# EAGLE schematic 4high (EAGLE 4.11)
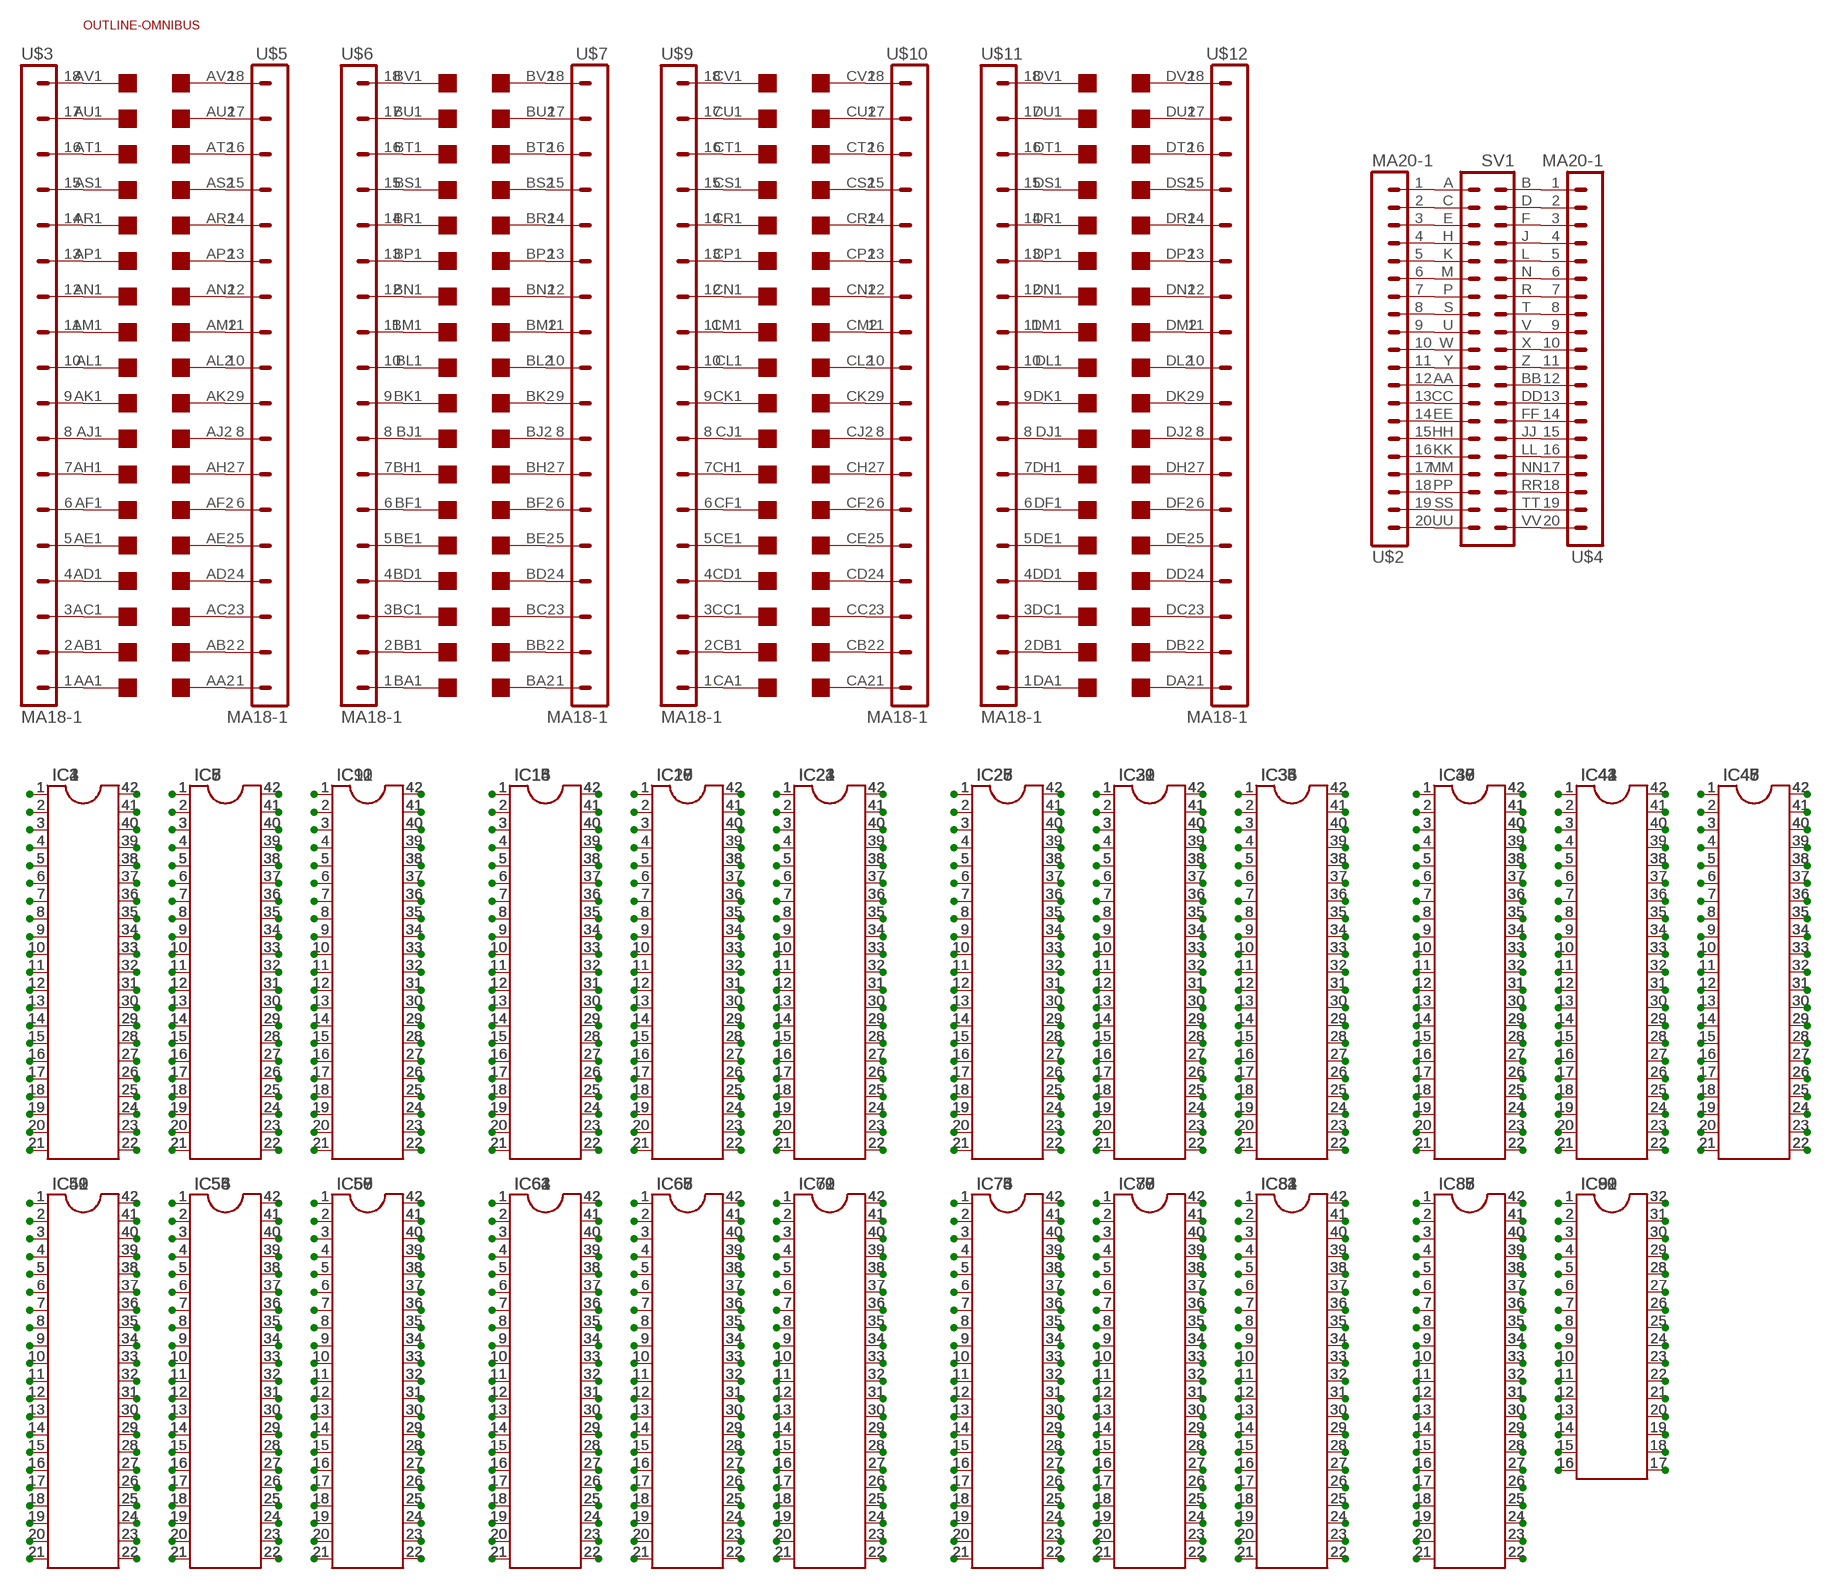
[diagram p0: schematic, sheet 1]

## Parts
IC1  DIL42  [DIL42]
IC2  DIL42  [DIL42]
IC3  DIL42  [DIL42]
IC4  DIL42  [DIL42]
IC5  DIL42  [DIL42]
IC6  DIL42  [DIL42]
IC7  DIL42  [DIL42]
IC8  DIL42  [DIL42]
IC9  DIL42  [DIL42]
IC10  DIL42  [DIL42]
IC11  DIL42  [DIL42]
IC12  DIL42  [DIL42]
IC13  DIL42  [DIL42]
IC14  DIL42  [DIL42]
IC15  DIL42  [DIL42]
IC16  DIL42  [DIL42]
IC17  DIL42  [DIL42]
IC18  DIL42  [DIL42]
IC19  DIL42  [DIL42]
IC20  DIL42  [DIL42]
IC21  DIL42  [DIL42]
IC22  DIL42  [DIL42]
IC23  DIL42  [DIL42]
IC24  DIL42  [DIL42]
IC25  DIL42  [DIL42]
IC26  DIL42  [DIL42]
IC27  DIL42  [DIL42]
IC28  DIL42  [DIL42]
IC29  DIL42  [DIL42]
IC30  DIL42  [DIL42]
IC31  DIL42  [DIL42]
IC32  DIL42  [DIL42]
IC33  DIL42  [DIL42]
IC34  DIL42  [DIL42]
IC35  DIL42  [DIL42]
IC36  DIL42  [DIL42]
IC37  DIL42  [DIL42]
IC38  DIL42  [DIL42]
IC39  DIL42  [DIL42]
IC40  DIL42  [DIL42]
IC41  DIL42  [DIL42]
IC42  DIL42  [DIL42]
IC43  DIL42  [DIL42]
IC44  DIL42  [DIL42]
IC45  DIL42  [DIL42]
IC46  DIL42  [DIL42]
IC47  DIL42  [DIL42]
IC48  DIL42  [DIL42]
IC49  DIL42  [DIL42]
IC50  DIL42  [DIL42]
IC51  DIL42  [DIL42]
IC52  DIL42  [DIL42]
IC53  DIL42  [DIL42]
IC54  DIL42  [DIL42]
IC55  DIL42  [DIL42]
IC56  DIL42  [DIL42]
IC57  DIL42  [DIL42]
IC58  DIL42  [DIL42]
IC59  DIL42  [DIL42]
IC60  DIL42  [DIL42]
IC61  DIL42  [DIL42]
IC62  DIL42  [DIL42]
IC63  DIL42  [DIL42]
IC64  DIL42  [DIL42]
IC65  DIL42  [DIL42]
IC66  DIL42  [DIL42]
IC67  DIL42  [DIL42]
IC68  DIL42  [DIL42]
IC69  DIL42  [DIL42]
IC70  DIL42  [DIL42]
IC71  DIL42  [DIL42]
IC72  DIL42  [DIL42]
IC73  DIL42  [DIL42]
IC74  DIL42  [DIL42]
IC75  DIL42  [DIL42]
IC76  DIL42  [DIL42]
IC77  DIL42  [DIL42]
IC78  DIL42  [DIL42]
IC79  DIL42  [DIL42]
IC80  DIL42  [DIL42]
IC81  DIL42  [DIL42]
IC82  DIL42  [DIL42]
IC83  DIL42  [DIL42]
IC84  DIL42  [DIL42]
IC85  DIL42  [DIL42]
IC86  DIL42  [DIL42]
IC87  DIL42  [DIL42]
IC88  DIL42  [DIL42]
IC89  DIL32  [DIL32]
IC90  DIL32  [DIL32]
IC91  DIL32  [DIL32]
IC92  DIL32  [DIL32]
SV1  DEC40PINH  [DEC40PINH]
U$1  QUAD  [EDGE-CON8]
U$2  MA20-1  [MA20-1]
U$3  MA18-1  [MA18-1]
U$4  MA20-1  [MA20-1]
U$5  MA18-1  [MA18-1]
U$6  MA18-1  [MA18-1]
U$7  MA18-1  [MA18-1]
U$8  OUTLINE-OMNIBUS  [OMNIBUS]
U$9  MA18-1  [MA18-1]
U$10  MA18-1  [MA18-1]
U$11  MA18-1  [MA18-1]
U$12  MA18-1  [MA18-1]

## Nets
GND [supply]: U$1.AC2 U$5.3
N$1: IC1.1 IC2.1 IC3.1 IC4.1
N$2: IC1.2 IC2.2 IC3.2 IC4.2
N$3: IC1.3 IC2.3 IC3.3 IC4.3
N$4: IC1.4 IC2.4 IC3.4 IC4.4
N$5: IC1.5 IC2.5 IC3.5 IC4.5
N$6: IC1.6 IC2.6 IC3.6 IC4.6
N$7: IC1.7 IC2.7 IC3.7 IC4.7
N$8: IC1.8 IC2.8 IC3.8 IC4.8
N$9: IC1.9 IC2.9 IC3.9 IC4.9
N$10: IC1.10 IC2.10 IC3.10 IC4.10
N$11: IC1.11 IC2.11 IC3.11 IC4.11
N$12: IC1.12 IC2.12 IC3.12 IC4.12
N$13: IC1.13 IC2.13 IC3.13 IC4.13
N$14: IC1.14 IC2.14 IC3.14 IC4.14
N$15: IC1.15 IC2.15 IC3.15 IC4.15
N$16: IC1.16 IC2.16 IC3.16 IC4.16
N$17: IC1.17 IC2.17 IC3.17 IC4.17
N$18: IC1.18 IC2.18 IC3.18 IC4.18
N$19: IC1.19 IC2.19 IC3.19 IC4.19
N$20: IC1.20 IC2.20 IC3.20 IC4.20
N$21: IC1.21 IC2.21 IC3.21 IC4.21
N$22: IC1.22 IC2.22 IC3.22 IC4.22
N$23: IC1.23 IC2.23 IC3.23 IC4.23
N$24: IC1.24 IC2.24 IC3.24 IC4.24
N$25: IC1.25 IC2.25 IC3.25 IC4.25
N$26: IC1.26 IC2.26 IC3.26 IC4.26
N$27: IC1.27 IC2.27 IC3.27 IC4.27
N$28: IC1.28 IC2.28 IC3.28 IC4.28
N$29: IC1.29 IC2.29 IC3.29 IC4.29
N$30: IC1.30 IC2.30 IC3.30 IC4.30
N$31: IC1.31 IC2.31 IC3.31 IC4.31
N$32: IC1.32 IC2.32 IC3.32 IC4.32
N$33: IC1.33 IC2.33 IC3.33 IC4.33
N$34: IC1.34 IC2.34 IC3.34 IC4.34
N$35: IC1.35 IC2.35 IC3.35 IC4.35
N$36: IC1.36 IC2.36 IC3.36 IC4.36
N$37: IC1.37 IC2.37 IC3.37 IC4.37
N$38: IC1.38 IC2.38 IC3.38 IC4.38
N$39: IC1.39 IC2.39 IC3.39 IC4.39
N$40: IC1.40 IC2.40 IC3.40 IC4.40
N$41: IC1.41 IC2.41 IC3.41 IC4.41
N$42: IC1.42 IC2.42 IC3.42 IC4.42
N$43: IC5.1 IC6.1 IC7.1 IC8.1
N$44: IC5.2 IC6.2 IC7.2 IC8.2
N$45: IC5.3 IC6.3 IC7.3 IC8.3
N$46: IC5.4 IC6.4 IC7.4 IC8.4
N$47: IC5.5 IC6.5 IC7.5 IC8.5
N$48: IC5.6 IC6.6 IC7.6 IC8.6
N$49: IC5.7 IC6.7 IC7.7 IC8.7
N$50: IC5.8 IC6.8 IC7.8 IC8.8
N$51: IC5.9 IC6.9 IC7.9 IC8.9
N$52: IC5.10 IC6.10 IC7.10 IC8.10
N$53: IC5.11 IC6.11 IC7.11 IC8.11
N$54: IC5.12 IC6.12 IC7.12 IC8.12
N$55: IC5.13 IC6.13 IC7.13 IC8.13
N$56: IC5.14 IC6.14 IC7.14 IC8.14
N$57: IC5.15 IC6.15 IC7.15 IC8.15
N$58: IC5.16 IC6.16 IC7.16 IC8.16
N$59: IC5.17 IC6.17 IC7.17 IC8.17
N$60: IC5.18 IC6.18 IC7.18 IC8.18
N$61: IC5.19 IC6.19 IC7.19 IC8.19
N$62: IC5.20 IC6.20 IC7.20 IC8.20
N$63: IC5.21 IC6.21 IC7.21 IC8.21
N$64: IC5.22 IC6.22 IC7.22 IC8.22
N$65: IC5.23 IC6.23 IC7.23 IC8.23
N$66: IC5.24 IC6.24 IC7.24 IC8.24
N$67: IC5.25 IC6.25 IC7.25 IC8.25
N$68: IC5.26 IC6.26 IC7.26 IC8.26
N$69: IC5.27 IC6.27 IC7.27 IC8.27
N$70: IC5.28 IC6.28 IC7.28 IC8.28
N$71: IC5.29 IC6.29 IC7.29 IC8.29
N$72: IC5.30 IC6.30 IC7.30 IC8.30
N$73: IC5.31 IC6.31 IC7.31 IC8.31
N$74: IC5.32 IC6.32 IC7.32 IC8.32
N$75: IC5.33 IC6.33 IC7.33 IC8.33
N$76: IC5.34 IC6.34 IC7.34 IC8.34
N$77: IC5.35 IC6.35 IC7.35 IC8.35
N$78: IC5.36 IC6.36 IC7.36 IC8.36
N$79: IC5.37 IC6.37 IC7.37 IC8.37
N$80: IC5.38 IC6.38 IC7.38 IC8.38
N$81: IC5.39 IC6.39 IC7.39 IC8.39
N$82: IC5.40 IC6.40 IC7.40 IC8.40
N$83: IC5.41 IC6.41 IC7.41 IC8.41
N$84: IC5.42 IC6.42 IC7.42 IC8.42
N$85: IC9.1 IC10.1 IC11.1 IC12.1
N$86: IC9.2 IC10.2 IC11.2 IC12.2
N$87: IC9.3 IC10.3 IC11.3 IC12.3
N$88: IC9.4 IC10.4 IC11.4 IC12.4
N$89: IC9.5 IC10.5 IC11.5 IC12.5
N$90: IC9.6 IC10.6 IC11.6 IC12.6
N$91: IC9.7 IC10.7 IC11.7 IC12.7
N$92: IC9.8 IC10.8 IC11.8 IC12.8
N$93: IC9.9 IC10.9 IC11.9 IC12.9
N$94: IC9.10 IC10.10 IC11.10 IC12.10
N$95: IC9.11 IC10.11 IC11.11 IC12.11
N$96: IC9.12 IC10.12 IC11.12 IC12.12
N$97: IC9.13 IC10.13 IC11.13 IC12.13
N$98: IC9.14 IC10.14 IC11.14 IC12.14
N$99: IC9.15 IC10.15 IC11.15 IC12.15
N$100: IC9.16 IC10.16 IC11.16 IC12.16
N$101: IC9.17 IC10.17 IC11.17 IC12.17
N$102: IC9.18 IC10.18 IC11.18 IC12.18
N$103: IC9.19 IC10.19 IC11.19 IC12.19
N$104: IC9.20 IC10.20 IC11.20 IC12.20
N$105: IC9.21 IC10.21 IC11.21 IC12.21
N$106: IC9.22 IC10.22 IC11.22 IC12.22
N$107: IC9.23 IC10.23 IC11.23 IC12.23
N$108: IC9.24 IC10.24 IC11.24 IC12.24
N$109: IC9.25 IC10.25 IC11.25 IC12.25
N$110: IC9.26 IC10.26 IC11.26 IC12.26
N$111: IC9.27 IC10.27 IC11.27 IC12.27
N$112: IC9.28 IC10.28 IC11.28 IC12.28
N$113: IC9.29 IC10.29 IC11.29 IC12.29
N$114: IC9.30 IC10.30 IC11.30 IC12.30
N$115: IC9.31 IC10.31 IC11.31 IC12.31
N$116: IC9.32 IC10.32 IC11.32 IC12.32
N$117: IC9.33 IC10.33 IC11.33 IC12.33
N$118: IC9.34 IC10.34 IC11.34 IC12.34
N$119: IC9.35 IC10.35 IC11.35 IC12.35
N$120: IC9.36 IC10.36 IC11.36 IC12.36
N$121: IC9.37 IC10.37 IC11.37 IC12.37
N$122: IC9.38 IC10.38 IC11.38 IC12.38
N$123: IC9.39 IC10.39 IC11.39 IC12.39
N$124: IC9.40 IC10.40 IC11.40 IC12.40
N$125: IC9.41 IC10.41 IC11.41 IC12.41
N$126: IC9.42 IC10.42 IC11.42 IC12.42
N$127: IC13.1 IC14.1 IC15.1 IC16.1
N$128: IC13.2 IC14.2 IC15.2 IC16.2
N$129: IC13.3 IC14.3 IC15.3 IC16.3
N$130: IC13.4 IC14.4 IC15.4 IC16.4
N$131: IC13.5 IC14.5 IC15.5 IC16.5
N$132: IC13.6 IC14.6 IC15.6 IC16.6
N$133: IC13.7 IC14.7 IC15.7 IC16.7
N$134: IC13.8 IC14.8 IC15.8 IC16.8
N$135: IC13.9 IC14.9 IC15.9 IC16.9
N$136: IC13.10 IC14.10 IC15.10 IC16.10
N$137: IC13.11 IC14.11 IC15.11 IC16.11
N$138: IC13.12 IC14.12 IC15.12 IC16.12
N$139: IC13.13 IC14.13 IC15.13 IC16.13
N$140: IC13.14 IC14.14 IC15.14 IC16.14
N$141: IC13.15 IC14.15 IC15.15 IC16.15
N$142: IC13.16 IC14.16 IC15.16 IC16.16
N$143: IC13.17 IC14.17 IC15.17 IC16.17
N$144: IC13.18 IC14.18 IC15.18 IC16.18
N$145: IC13.19 IC14.19 IC15.19 IC16.19
N$146: IC13.20 IC14.20 IC15.20 IC16.20
N$147: IC13.21 IC14.21 IC15.21 IC16.21
N$148: IC13.22 IC14.22 IC15.22 IC16.22
N$149: IC13.23 IC14.23 IC15.23 IC16.23
N$150: IC13.24 IC14.24 IC15.24 IC16.24
N$151: IC13.25 IC14.25 IC15.25 IC16.25
N$152: IC13.26 IC14.26 IC15.26 IC16.26
N$153: IC13.27 IC14.27 IC15.27 IC16.27
N$154: IC13.28 IC14.28 IC15.28 IC16.28
N$155: IC13.29 IC14.29 IC15.29 IC16.29
N$156: IC13.30 IC14.30 IC15.30 IC16.30
N$157: IC13.31 IC14.31 IC15.31 IC16.31
N$158: IC13.32 IC14.32 IC15.32 IC16.32
N$159: IC13.33 IC14.33 IC15.33 IC16.33
N$160: IC13.34 IC14.34 IC15.34 IC16.34
N$161: IC13.35 IC14.35 IC15.35 IC16.35
N$162: IC13.36 IC14.36 IC15.36 IC16.36
N$163: IC13.37 IC14.37 IC15.37 IC16.37
N$164: IC13.38 IC14.38 IC15.38 IC16.38
N$165: IC13.39 IC14.39 IC15.39 IC16.39
N$166: IC13.40 IC14.40 IC15.40 IC16.40
N$167: IC13.41 IC14.41 IC15.41 IC16.41
N$168: IC13.42 IC14.42 IC15.42 IC16.42
N$169: U$1.AK1 U$3.9
N$170: U$1.AL1 U$3.10
N$171: U$1.AM1 U$3.11
N$172: U$1.AN1 U$3.12
N$173: U$1.AP1 U$3.13
N$174: U$1.AR1 U$3.14
N$175: U$1.AS1 U$3.15
N$176: U$1.AT1 U$3.16
N$177: U$1.AU1 U$3.17
N$178: U$1.AV1 U$3.18
N$179: U$1.AJ1 U$3.8
N$180: U$1.AH1 U$3.7
N$181: U$1.AF1 U$3.6
N$182: U$1.AE1 U$3.5
N$183: U$1.AD1 U$3.4
N$184: U$1.AC1 U$3.3
N$185: U$1.AB1 U$3.2
N$186: U$1.AA1 U$3.1
N$187: U$1.AL2 U$5.10
N$188: U$1.AM2 U$5.11
N$189: U$1.AN2 U$5.12
N$190: U$1.AP2 U$5.13
N$191: U$1.AR2 U$5.14
N$192: U$1.AS2 U$5.15
N$193: U$1.AT2 U$5.16
N$194: U$1.AK2 U$5.9
N$195: U$1.AJ2 U$5.8
N$196: U$1.AH2 U$5.7
N$197: U$1.AF2 U$5.6
N$198: U$1.AE2 U$5.5
N$199: U$1.AD2 U$5.4
N$200: IC17.1 IC18.1 IC19.1 IC20.1
N$201: U$1.AU2 U$5.17
N$202: U$1.AV2 U$5.18
N$203: U$1.AB2 U$5.2
N$204: IC17.2 IC18.2 IC19.2 IC20.2
N$205: IC17.3 IC18.3 IC19.3 IC20.3
N$206: IC17.4 IC18.4 IC19.4 IC20.4
N$207: IC17.5 IC18.5 IC19.5 IC20.5
N$208: IC17.6 IC18.6 IC19.6 IC20.6
N$209: IC17.7 IC18.7 IC19.7 IC20.7
N$210: IC17.8 IC18.8 IC19.8 IC20.8
N$211: IC17.9 IC18.9 IC19.9 IC20.9
N$212: IC17.10 IC18.10 IC19.10 IC20.10
N$213: IC17.11 IC18.11 IC19.11 IC20.11
N$214: IC17.12 IC18.12 IC19.12 IC20.12
N$215: IC17.13 IC18.13 IC19.13 IC20.13
N$216: IC17.14 IC18.14 IC19.14 IC20.14
N$217: IC17.15 IC18.15 IC19.15 IC20.15
N$218: IC17.16 IC18.16 IC19.16 IC20.16
N$219: IC17.17 IC18.17 IC19.17 IC20.17
N$220: IC17.18 IC18.18 IC19.18 IC20.18
N$221: IC17.19 IC18.19 IC19.19 IC20.19
N$222: IC17.20 IC18.20 IC19.20 IC20.20
N$223: IC17.21 IC18.21 IC19.21 IC20.21
N$224: IC17.22 IC18.22 IC19.22 IC20.22
N$225: IC17.23 IC18.23 IC19.23 IC20.23
N$226: IC17.24 IC18.24 IC19.24 IC20.24
N$227: IC17.25 IC18.25 IC19.25 IC20.25
N$228: IC17.26 IC18.26 IC19.26 IC20.26
N$229: IC17.27 IC18.27 IC19.27 IC20.27
N$230: IC17.28 IC18.28 IC19.28 IC20.28
N$231: IC17.29 IC18.29 IC19.29 IC20.29
N$232: IC17.30 IC18.30 IC19.30 IC20.30
N$233: IC17.31 IC18.31 IC19.31 IC20.31
N$234: IC17.32 IC18.32 IC19.32 IC20.32
N$235: IC17.33 IC18.33 IC19.33 IC20.33
N$236: IC17.34 IC18.34 IC19.34 IC20.34
N$237: IC17.35 IC18.35 IC19.35 IC20.35
N$238: IC17.36 IC18.36 IC19.36 IC20.36
N$239: IC17.37 IC18.37 IC19.37 IC20.37
N$240: IC17.38 IC18.38 IC19.38 IC20.38
N$241: IC17.39 IC18.39 IC19.39 IC20.39
N$242: IC17.40 IC18.40 IC19.40 IC20.40
N$243: IC17.41 IC18.41 IC19.41 IC20.41
N$244: IC17.42 IC18.42 IC19.42 IC20.42
N$245: IC21.1 IC22.1 IC23.1 IC24.1
N$246: IC21.2 IC22.2 IC23.2 IC24.2
N$247: IC21.3 IC22.3 IC23.3 IC24.3
N$248: IC21.4 IC22.4 IC23.4 IC24.4
N$249: IC21.5 IC22.5 IC23.5 IC24.5
N$250: IC21.6 IC22.6 IC23.6 IC24.6
N$251: IC21.7 IC22.7 IC23.7 IC24.7
N$252: IC21.8 IC22.8 IC23.8 IC24.8
N$253: IC21.9 IC22.9 IC23.9 IC24.9
N$254: IC21.10 IC22.10 IC23.10 IC24.10
N$255: IC21.11 IC22.11 IC23.11 IC24.11
N$256: IC21.12 IC22.12 IC23.12 IC24.12
N$257: IC21.13 IC22.13 IC23.13 IC24.13
N$258: IC21.14 IC22.14 IC23.14 IC24.14
N$259: IC21.15 IC22.15 IC23.15 IC24.15
N$260: IC21.16 IC22.16 IC23.16 IC24.16
N$261: IC21.17 IC22.17 IC23.17 IC24.17
N$262: IC21.18 IC22.18 IC23.18 IC24.18
N$263: IC21.19 IC22.19 IC23.19 IC24.19
N$264: IC21.20 IC22.20 IC23.20 IC24.20
N$265: IC21.21 IC22.21 IC23.21 IC24.21
N$266: IC21.22 IC22.22 IC23.22 IC24.22
N$267: IC21.23 IC22.23 IC23.23 IC24.23
N$268: IC21.24 IC22.24 IC23.24 IC24.24
N$269: IC21.25 IC22.25 IC23.25 IC24.25
N$270: IC21.26 IC22.26 IC23.26 IC24.26
N$271: IC21.27 IC22.27 IC23.27 IC24.27
N$272: IC21.28 IC22.28 IC23.28 IC24.28
N$273: IC21.29 IC22.29 IC23.29 IC24.29
N$274: IC21.30 IC22.30 IC23.30 IC24.30
N$275: IC21.31 IC22.31 IC23.31 IC24.31
N$276: IC21.32 IC22.32 IC23.32 IC24.32
N$277: IC21.33 IC22.33 IC23.33 IC24.33
N$278: IC21.34 IC22.34 IC23.34 IC24.34
N$279: IC21.35 IC22.35 IC23.35 IC24.35
N$280: IC21.36 IC22.36 IC23.36 IC24.36
N$281: IC21.37 IC22.37 IC23.37 IC24.37
N$282: IC21.38 IC22.38 IC23.38 IC24.38
N$283: IC21.39 IC22.39 IC23.39 IC24.39
N$284: IC21.40 IC22.40 IC23.40 IC24.40
N$285: IC21.41 IC22.41 IC23.41 IC24.41
N$286: IC21.42 IC22.42 IC23.42 IC24.42
N$287: IC25.1 IC26.1 IC27.1 IC28.1
N$288: IC25.2 IC26.2 IC27.2 IC28.2
N$289: IC25.3 IC26.3 IC27.3 IC28.3
N$290: IC25.4 IC26.4 IC27.4 IC28.4
N$291: IC25.5 IC26.5 IC27.5 IC28.5
N$292: IC25.6 IC26.6 IC27.6 IC28.6
N$293: IC25.7 IC26.7 IC27.7 IC28.7
N$294: IC25.8 IC26.8 IC27.8 IC28.8
N$295: IC25.9 IC26.9 IC27.9 IC28.9
N$296: IC25.10 IC26.10 IC27.10 IC28.10
N$297: IC25.11 IC26.11 IC27.11 IC28.11
N$298: IC25.12 IC26.12 IC27.12 IC28.12
N$299: IC25.13 IC26.13 IC27.13 IC28.13
N$300: IC25.14 IC26.14 IC27.14 IC28.14
N$301: IC25.15 IC26.15 IC27.15 IC28.15
N$302: IC25.16 IC26.16 IC27.16 IC28.16
N$303: IC25.17 IC26.17 IC27.17 IC28.17
N$304: IC25.18 IC26.18 IC27.18 IC28.18
N$305: IC25.19 IC26.19 IC27.19 IC28.19
N$306: IC25.20 IC26.20 IC27.20 IC28.20
N$307: IC25.21 IC26.21 IC27.21 IC28.21
N$308: IC25.22 IC26.22 IC27.22 IC28.22
N$309: IC25.23 IC26.23 IC27.23 IC28.23
N$310: IC25.24 IC26.24 IC27.24 IC28.24
N$311: IC25.25 IC26.25 IC27.25 IC28.25
N$312: IC25.26 IC26.26 IC27.26 IC28.26
N$313: IC25.27 IC26.27 IC27.27 IC28.27
N$314: IC25.28 IC26.28 IC27.28 IC28.28
N$315: IC25.29 IC26.29 IC27.29 IC28.29
N$316: IC25.30 IC26.30 IC27.30 IC28.30
N$317: IC25.31 IC26.31 IC27.31 IC28.31
N$318: IC25.32 IC26.32 IC27.32 IC28.32
N$319: IC25.33 IC26.33 IC27.33 IC28.33
N$320: IC25.34 IC26.34 IC27.34 IC28.34
N$321: IC25.35 IC26.35 IC27.35 IC28.35
N$322: IC25.36 IC26.36 IC27.36 IC28.36
N$323: IC25.37 IC26.37 IC27.37 IC28.37
N$324: IC25.38 IC26.38 IC27.38 IC28.38
N$325: IC25.39 IC26.39 IC27.39 IC28.39
N$326: IC25.40 IC26.40 IC27.40 IC28.40
N$327: IC25.41 IC26.41 IC27.41 IC28.41
N$328: IC25.42 IC26.42 IC27.42 IC28.42
N$329: IC29.1 IC30.1 IC31.1 IC32.1
N$330: IC29.2 IC30.2 IC31.2 IC32.2
N$331: IC29.3 IC30.3 IC31.3 IC32.3
N$332: IC29.4 IC30.4 IC31.4 IC32.4
N$333: IC29.5 IC30.5 IC31.5 IC32.5
N$334: IC29.6 IC30.6 IC31.6 IC32.6
N$335: IC29.7 IC30.7 IC31.7 IC32.7
N$336: IC29.8 IC30.8 IC31.8 IC32.8
N$337: IC29.9 IC30.9 IC31.9 IC32.9
N$338: IC29.10 IC30.10 IC31.10 IC32.10
N$339: IC29.11 IC30.11 IC31.11 IC32.11
N$340: IC29.12 IC30.12 IC31.12 IC32.12
N$341: IC29.13 IC30.13 IC31.13 IC32.13
N$342: IC29.14 IC30.14 IC31.14 IC32.14
N$343: IC29.15 IC30.15 IC31.15 IC32.15
N$344: IC29.16 IC30.16 IC31.16 IC32.16
N$345: IC29.17 IC30.17 IC31.17 IC32.17
N$346: IC29.18 IC30.18 IC31.18 IC32.18
N$347: IC29.19 IC30.19 IC31.19 IC32.19
N$348: IC29.20 IC30.20 IC31.20 IC32.20
N$349: IC29.21 IC30.21 IC31.21 IC32.21
N$350: IC29.22 IC30.22 IC31.22 IC32.22
N$351: IC29.23 IC30.23 IC31.23 IC32.23
N$352: IC29.24 IC30.24 IC31.24 IC32.24
N$353: IC29.25 IC30.25 IC31.25 IC32.25
N$354: IC29.26 IC30.26 IC31.26 IC32.26
N$355: IC29.27 IC30.27 IC31.27 IC32.27
N$356: IC29.28 IC30.28 IC31.28 IC32.28
N$357: IC29.29 IC30.29 IC31.29 IC32.29
N$358: IC29.30 IC30.30 IC31.30 IC32.30
N$359: IC29.31 IC30.31 IC31.31 IC32.31
N$360: IC29.32 IC30.32 IC31.32 IC32.32
N$361: IC29.33 IC30.33 IC31.33 IC32.33
N$362: IC29.34 IC30.34 IC31.34 IC32.34
N$363: IC29.35 IC30.35 IC31.35 IC32.35
N$364: IC29.36 IC30.36 IC31.36 IC32.36
N$365: IC29.37 IC30.37 IC31.37 IC32.37
N$366: IC29.38 IC30.38 IC31.38 IC32.38
N$367: IC29.39 IC30.39 IC31.39 IC32.39
N$368: IC29.40 IC30.40 IC31.40 IC32.40
N$369: IC29.41 IC30.41 IC31.41 IC32.41
N$370: IC29.42 IC30.42 IC31.42 IC32.42
N$371: IC33.1 IC34.1 IC35.1 IC36.1
N$372: IC33.2 IC34.2 IC35.2 IC36.2
N$373: U$1.BV1 U$6.18
N$374: U$1.BU1 U$6.17
N$375: U$1.BT1 U$6.16
N$376: U$1.BS1 U$6.15
N$377: U$1.BR1 U$6.14
N$378: U$1.BP1 U$6.13
N$379: U$1.BN1 U$6.12
N$380: U$1.BM1 U$6.11
N$381: U$1.BL1 U$6.10
N$382: U$1.BK1 U$6.9
N$383: U$1.BJ1 U$6.8
N$384: U$1.BH1 U$6.7
N$385: U$1.BF1 U$6.6
N$386: U$1.BE1 U$6.5
N$387: U$1.BD1 U$6.4
N$388: U$1.BC1 U$6.3
N$389: U$1.BB1 U$6.2
N$390: U$1.BA1 U$6.1
N$391: U$1.BV2 U$7.18
N$392: U$1.BU2 U$7.17
N$393: U$1.BT2 U$7.16
N$394: U$1.BS2 U$7.15
N$395: U$1.BR2 U$7.14
N$396: U$1.BP2 U$7.13
N$397: U$1.BN2 U$7.12
N$398: U$1.BM2 U$7.11
N$399: U$1.BL2 U$7.10
N$400: U$1.BK2 U$7.9
N$401: U$1.BJ2 U$7.8
N$402: U$1.BH2 U$7.7
N$403: U$1.BF2 U$7.6
N$404: U$1.BE2 U$7.5
N$405: U$1.BD2 U$7.4
N$406: U$1.BC2 U$7.3
N$407: U$1.BB2 U$7.2
N$408: U$1.BA2 U$7.1
N$409: U$1.CV1 U$9.18
N$410: U$1.CU1 U$9.17
N$411: U$1.CT1 U$9.16
N$412: U$1.CS1 U$9.15
N$413: U$1.CR1 U$9.14
N$414: U$1.CP1 U$9.13
N$415: U$1.CN1 U$9.12
N$416: U$1.CM1 U$9.11
N$417: U$1.CL1 U$9.10
N$418: U$1.CK1 U$9.9
N$419: U$1.CJ1 U$9.8
N$420: U$1.CH1 U$9.7
N$421: U$1.CF1 U$9.6
N$422: U$1.CE1 U$9.5
N$423: U$1.CD1 U$9.4
N$424: U$1.CC1 U$9.3
N$425: U$1.CB1 U$9.2
N$426: U$1.CA1 U$9.1
N$427: U$1.CV2 U$10.18
N$428: U$1.CU2 U$10.17
N$429: U$1.CT2 U$10.16
N$430: U$1.CS2 U$10.15
N$431: U$1.CR2 U$10.14
N$432: U$1.CP2 U$10.13
N$433: U$1.CN2 U$10.12
N$434: U$1.CM2 U$10.11
N$435: U$1.CL2 U$10.10
N$436: U$1.CK2 U$10.9
N$437: U$1.CJ2 U$10.8
N$438: U$1.CH2 U$10.7
N$439: U$1.CF2 U$10.6
N$440: U$1.CE2 U$10.5
N$441: U$1.CD2 U$10.4
N$442: U$1.CC2 U$10.3
N$443: U$1.CB2 U$10.2
N$444: U$1.CA2 U$10.1
N$445: U$1.DV1 U$11.18
N$446: U$1.DU1 U$11.17
N$447: U$1.DT1 U$11.16
N$448: U$1.DS1 U$11.15
N$449: U$1.DR1 U$11.14
N$450: U$1.DP1 U$11.13
N$451: U$1.DN1 U$11.12
N$452: U$1.DM1 U$11.11
N$453: U$1.DL1 U$11.10
N$454: U$1.DK1 U$11.9
N$455: U$1.DJ1 U$11.8
N$456: U$1.DH1 U$11.7
N$457: U$1.DF1 U$11.6
N$458: U$1.DE1 U$11.5
N$459: U$1.DD1 U$11.4
N$460: U$1.DC1 U$11.3
N$461: U$1.DB1 U$11.2
N$462: U$1.DA1 U$11.1
N$463: U$1.DV2 U$12.18
N$464: U$1.DU2 U$12.17
N$465: U$1.DT2 U$12.16
N$466: U$1.DS2 U$12.15
N$467: U$1.DR2 U$12.14
N$468: U$1.DP2 U$12.13
N$469: U$1.DN2 U$12.12
N$470: U$1.DM2 U$12.11
N$471: U$1.DL2 U$12.10
N$472: U$1.DK2 U$12.9
N$473: U$1.DJ2 U$12.8
N$474: U$1.DH2 U$12.7
N$475: U$1.DF2 U$12.6
N$476: U$1.DE2 U$12.5
N$477: U$1.DD2 U$12.4
N$478: U$1.DC2 U$12.3
N$479: U$1.DB2 U$12.2
N$480: U$1.DA2 U$12.1
N$481: IC33.3 IC34.3 IC35.3 IC36.3
N$482: IC33.4 IC34.4 IC35.4 IC36.4
N$483: IC33.5 IC34.5 IC35.5 IC36.5
N$484: IC33.6 IC34.6 IC35.6 IC36.6
N$485: IC33.7 IC34.7 IC35.7 IC36.7
N$486: IC33.8 IC34.8 IC35.8 IC36.8
N$487: IC33.9 IC34.9 IC35.9 IC36.9
N$488: IC33.10 IC34.10 IC35.10 IC36.10
N$489: IC33.11 IC34.11 IC35.11 IC36.11
N$490: IC33.12 IC34.12 IC35.12 IC36.12
N$491: IC33.13 IC34.13 IC35.13 IC36.13
N$492: IC33.14 IC34.14 IC35.14 IC36.14
N$493: IC33.15 IC34.15 IC35.15 IC36.15
N$494: IC33.16 IC34.16 IC35.16 IC36.16
N$495: IC33.17 IC34.17 IC35.17 IC36.17
N$496: IC33.18 IC34.18 IC35.18 IC36.18
N$497: IC33.19 IC34.19 IC35.19 IC36.19
N$498: IC33.20 IC34.20 IC35.20 IC36.20
N$499: IC33.21 IC34.21 IC35.21 IC36.21
N$500: IC33.22 IC34.22 IC35.22 IC36.22
N$501: IC33.23 IC34.23 IC35.23 IC36.23
N$502: IC33.24 IC34.24 IC35.24 IC36.24
N$503: IC33.25 IC34.25 IC35.25 IC36.25
N$504: IC33.26 IC34.26 IC35.26 IC36.26
N$505: IC33.27 IC34.27 IC35.27 IC36.27
N$506: IC33.28 IC34.28 IC35.28 IC36.28
N$507: IC33.29 IC34.29 IC35.29 IC36.29
N$508: IC33.30 IC34.30 IC35.30 IC36.30
N$509: IC33.31 IC34.31 IC35.31 IC36.31
N$510: IC33.32 IC34.32 IC35.32 IC36.32
N$511: IC33.33 IC34.33 IC35.33 IC36.33
N$512: IC33.34 IC34.34 IC35.34 IC36.34
N$513: IC33.35 IC34.35 IC35.35 IC36.35
N$514: IC33.36 IC34.36 IC35.36 IC36.36
N$515: IC33.37 IC34.37 IC35.37 IC36.37
N$516: IC33.38 IC34.38 IC35.38 IC36.38
N$517: IC33.39 IC34.39 IC35.39 IC36.39
N$518: IC33.40 IC34.40 IC35.40 IC36.40
N$519: IC33.41 IC34.41 IC35.41 IC36.41
N$520: IC33.42 IC34.42 IC35.42 IC36.42
N$521: IC37.1 IC38.1 IC39.1 IC40.1
N$522: IC37.2 IC38.2 IC39.2 IC40.2
N$523: IC37.3 IC38.3 IC39.3 IC40.3
N$524: IC37.4 IC38.4 IC39.4 IC40.4
N$525: IC37.5 IC38.5 IC39.5 IC40.5
N$526: IC37.6 IC38.6 IC39.6 IC40.6
N$527: IC37.7 IC38.7 IC39.7 IC40.7
N$528: IC37.8 IC38.8 IC39.8 IC40.8
N$529: IC37.9 IC38.9 IC39.9 IC40.9
N$530: IC37.10 IC38.10 IC39.10 IC40.10
N$531: IC37.11 IC38.11 IC39.11 IC40.11
N$532: IC37.12 IC38.12 IC39.12 IC40.12
N$533: IC37.13 IC38.13 IC39.13 IC40.13
N$534: IC37.14 IC38.14 IC39.14 IC40.14
N$535: IC37.15 IC38.15 IC39.15 IC40.15
N$536: IC37.16 IC38.16 IC39.16 IC40.16
N$537: IC37.17 IC38.17 IC39.17 IC40.17
N$538: IC37.18 IC38.18 IC39.18 IC40.18
N$539: IC37.19 IC38.19 IC39.19 IC40.19
N$540: IC37.20 IC38.20 IC39.20 IC40.20
N$541: IC37.21 IC38.21 IC39.21 IC40.21
N$542: IC37.22 IC38.22 IC39.22 IC40.22
N$543: IC37.23 IC38.23 IC39.23 IC40.23
N$544: IC37.24 IC38.24 IC39.24 IC40.24
N$545: IC37.25 IC38.25 IC39.25 IC40.25
N$546: IC37.26 IC38.26 IC39.26 IC40.26
N$547: IC37.27 IC38.27 IC39.27 IC40.27
N$548: IC37.28 IC38.28 IC39.28 IC40.28
N$549: IC37.29 IC38.29 IC39.29 IC40.29
N$550: IC37.30 IC38.30 IC39.30 IC40.30
N$551: IC37.31 IC38.31 IC39.31 IC40.31
N$552: IC37.32 IC38.32 IC39.32 IC40.32
N$553: IC37.33 IC38.33 IC39.33 IC40.33
N$554: IC37.34 IC38.34 IC39.34 IC40.34
N$555: IC37.35 IC38.35 IC39.35 IC40.35
N$556: IC37.36 IC38.36 IC39.36 IC40.36
N$557: IC37.37 IC38.37 IC39.37 IC40.37
N$558: IC37.38 IC38.38 IC39.38 IC40.38
N$559: IC37.39 IC38.39 IC39.39 IC40.39
N$560: IC37.40 IC38.40 IC39.40 IC40.40
N$561: IC37.41 IC38.41 IC39.41 IC40.41
N$562: IC37.42 IC38.42 IC39.42 IC40.42
N$563: IC41.1 IC42.1 IC43.1 IC44.1
N$564: IC41.2 IC42.2 IC43.2 IC44.2
N$565: IC41.3 IC42.3 IC43.3 IC44.3
N$566: IC41.4 IC42.4 IC43.4 IC44.4
N$567: IC41.5 IC42.5 IC43.5 IC44.5
N$568: IC41.6 IC42.6 IC43.6 IC44.6
N$569: IC41.7 IC42.7 IC43.7 IC44.7
N$570: IC41.8 IC42.8 IC43.8 IC44.8
N$571: IC41.9 IC42.9 IC43.9 IC44.9
N$572: IC41.10 IC42.10 IC43.10 IC44.10
N$573: IC41.11 IC42.11 IC43.11 IC44.11
N$574: IC41.12 IC42.12 IC43.12 IC44.12
N$575: IC41.13 IC42.13 IC43.13 IC44.13
N$576: IC41.14 IC42.14 IC43.14 IC44.14
N$577: IC41.15 IC42.15 IC43.15 IC44.15
N$578: IC41.16 IC42.16 IC43.16 IC44.16
N$579: IC41.17 IC42.17 IC43.17 IC44.17
N$580: IC41.18 IC42.18 IC43.18 IC44.18
N$581: IC41.19 IC42.19 IC43.19 IC44.19
N$582: IC41.20 IC42.20 IC43.20 IC44.20
N$583: IC41.21 IC42.21 IC43.21 IC44.21
N$584: IC41.22 IC42.22 IC43.22 IC44.22
N$585: IC41.23 IC42.23 IC43.23 IC44.23
N$586: IC41.24 IC42.24 IC43.24 IC44.24
N$587: IC41.25 IC42.25 IC43.25 IC44.25
N$588: IC41.26 IC42.26 IC43.26 IC44.26
N$589: IC41.27 IC42.27 IC43.27 IC44.27
N$590: IC41.28 IC42.28 IC43.28 IC44.28
N$591: IC41.29 IC42.29 IC43.29 IC44.29
N$592: IC41.30 IC42.30 IC43.30 IC44.30
N$593: IC41.31 IC42.31 IC43.31 IC44.31
N$594: IC41.32 IC42.32 IC43.32 IC44.32
N$595: IC41.33 IC42.33 IC43.33 IC44.33
N$596: IC41.34 IC42.34 IC43.34 IC44.34
N$597: IC41.35 IC42.35 IC43.35 IC44.35
N$598: IC41.36 IC42.36 IC43.36 IC44.36
N$599: IC41.37 IC42.37 IC43.37 IC44.37
N$600: IC41.38 IC42.38 IC43.38 IC44.38
N$601: IC41.39 IC42.39 IC43.39 IC44.39
N$602: IC41.40 IC42.40 IC43.40 IC44.40
N$603: IC41.41 IC42.41 IC43.41 IC44.41
N$604: IC41.42 IC42.42 IC43.42 IC44.42
N$605: IC45.1 IC46.1 IC47.1 IC48.1
N$606: IC45.2 IC46.2 IC47.2 IC48.2
N$607: IC45.3 IC46.3 IC47.3 IC48.3
N$608: IC45.4 IC46.4 IC47.4 IC48.4
N$609: IC45.5 IC46.5 IC47.5 IC48.5
N$610: IC45.6 IC46.6 IC47.6 IC48.6
N$611: IC45.7 IC46.7 IC47.7 IC48.7
N$612: IC45.8 IC46.8 IC47.8 IC48.8
N$613: IC45.9 IC46.9 IC47.9 IC48.9
N$614: IC45.10 IC46.10 IC47.10 IC48.10
N$615: IC45.11 IC46.11 IC47.11 IC48.11
N$616: IC45.12 IC46.12 IC47.12 IC48.12
N$617: IC45.13 IC46.13 IC47.13 IC48.13
N$618: IC45.14 IC46.14 IC47.14 IC48.14
N$619: IC45.15 IC46.15 IC47.15 IC48.15
N$620: IC45.16 IC46.16 IC47.16 IC48.16
N$621: IC45.17 IC46.17 IC47.17 IC48.17
N$622: IC45.18 IC46.18 IC47.18 IC48.18
N$623: IC45.19 IC46.19 IC47.19 IC48.19
N$624: IC45.20 IC46.20 IC47.20 IC48.20
N$625: IC45.21 IC46.21 IC47.21 IC48.21
N$626: IC45.22 IC46.22 IC47.22 IC48.22
N$627: IC45.23 IC46.23 IC47.23 IC48.23
N$628: IC45.24 IC46.24 IC47.24 IC48.24
N$629: IC45.25 IC46.25 IC47.25 IC48.25
N$630: IC45.26 IC46.26 IC47.26 IC48.26
N$631: IC45.27 IC46.27 IC47.27 IC48.27
N$632: IC45.28 IC46.28 IC47.28 IC48.28
N$633: IC45.29 IC46.29 IC47.29 IC48.29
N$634: IC45.30 IC46.30 IC47.30 IC48.30
N$635: IC45.31 IC46.31 IC47.31 IC48.31
N$636: IC45.32 IC46.32 IC47.32 IC48.32
N$637: IC45.33 IC46.33 IC47.33 IC48.33
N$638: IC45.34 IC46.34 IC47.34 IC48.34
N$639: IC45.35 IC46.35 IC47.35 IC48.35
N$640: IC45.36 IC46.36 IC47.36 IC48.36
N$641: IC45.37 IC46.37 IC47.37 IC48.37
N$642: IC45.38 IC46.38 IC47.38 IC48.38
N$643: IC45.39 IC46.39 IC47.39 IC48.39
N$644: IC45.40 IC46.40 IC47.40 IC48.40
N$645: IC45.41 IC46.41 IC47.41 IC48.41
N$646: IC45.42 IC46.42 IC47.42 IC48.42
N$647: IC49.1 IC50.1 IC51.1 IC52.1
N$648: IC49.2 IC50.2 IC51.2 IC52.2
N$649: IC49.3 IC50.3 IC51.3 IC52.3
N$650: IC49.4 IC50.4 IC51.4 IC52.4
N$651: IC49.5 IC50.5 IC51.5 IC52.5
N$652: IC49.6 IC50.6 IC51.6 IC52.6
N$653: IC49.7 IC50.7 IC51.7 IC52.7
N$654: IC49.8 IC50.8 IC51.8 IC52.8
N$655: IC49.9 IC50.9 IC51.9 IC52.9
N$656: IC49.10 IC50.10 IC51.10 IC52.10
N$657: IC49.11 IC50.11 IC51.11 IC52.11
N$658: IC49.12 IC50.12 IC51.12 IC52.12
N$659: IC49.13 IC50.13 IC51.13 IC52.13
N$660: IC49.14 IC50.14 IC51.14 IC52.14
N$661: IC49.15 IC50.15 IC51.15 IC52.15
N$662: IC49.16 IC50.16 IC51.16 IC52.16
N$663: IC49.17 IC50.17 IC51.17 IC52.17
N$664: IC49.18 IC50.18 IC51.18 IC52.18
N$665: IC49.19 IC50.19 IC51.19 IC52.19
N$666: IC49.20 IC50.20 IC51.20 IC52.20
N$667: IC49.21 IC50.21 IC51.21 IC52.21
N$668: IC49.22 IC50.22 IC51.22 IC52.22
N$669: IC49.23 IC50.23 IC51.23 IC52.23
N$670: IC49.24 IC50.24 IC51.24 IC52.24
N$671: IC49.25 IC50.25 IC51.25 IC52.25
N$672: IC49.26 IC50.26 IC51.26 IC52.26
N$673: IC49.27 IC50.27 IC51.27 IC52.27
N$674: IC49.28 IC50.28 IC51.28 IC52.28
N$675: IC49.29 IC50.29 IC51.29 IC52.29
N$676: IC49.30 IC50.30 IC51.30 IC52.30
N$677: IC49.31 IC50.31 IC51.31 IC52.31
N$678: IC49.32 IC50.32 IC51.32 IC52.32
N$679: IC49.33 IC50.33 IC51.33 IC52.33
N$680: IC49.34 IC50.34 IC51.34 IC52.34
N$681: IC49.35 IC50.35 IC51.35 IC52.35
N$682: IC49.36 IC50.36 IC51.36 IC52.36
N$683: IC49.37 IC50.37 IC51.37 IC52.37
N$684: IC49.38 IC50.38 IC51.38 IC52.38
N$685: IC49.39 IC50.39 IC51.39 IC52.39
N$686: IC49.40 IC50.40 IC51.40 IC52.40
N$687: IC49.41 IC50.41 IC51.41 IC52.41
N$688: IC49.42 IC50.42 IC51.42 IC52.42
N$689: IC53.1 IC54.1 IC55.1 IC56.1
N$690: IC53.2 IC54.2 IC55.2 IC56.2
N$691: IC53.3 IC54.3 IC55.3 IC56.3
N$692: IC53.4 IC54.4 IC55.4 IC56.4
N$693: IC53.5 IC54.5 IC55.5 IC56.5
N$694: IC53.6 IC54.6 IC55.6 IC56.6
N$695: IC53.7 IC54.7 IC55.7 IC56.7
N$696: IC53.8 IC54.8 IC55.8 IC56.8
N$697: IC53.9 IC54.9 IC55.9 IC56.9
N$698: IC53.10 IC54.10 IC55.10 IC56.10
N$699: IC53.11 IC54.11 IC55.11 IC56.11
N$700: IC53.12 IC54.12 IC55.12 IC56.12
N$701: IC53.13 IC54.13 IC55.13 IC56.13
N$702: IC53.14 IC54.14 IC55.14 IC56.14
N$703: IC53.15 IC54.15 IC55.15 IC56.15
N$704: IC53.16 IC54.16 IC55.16 IC56.16
N$705: IC53.17 IC54.17 IC55.17 IC56.17
N$706: IC53.18 IC54.18 IC55.18 IC56.18
N$707: IC53.19 IC54.19 IC55.19 IC56.19
N$708: IC53.20 IC54.20 IC55.20 IC56.20
N$709: IC53.21 IC54.21 IC55.21 IC56.21
N$710: IC53.22 IC54.22 IC55.22 IC56.22
N$711: IC53.23 IC54.23 IC55.23 IC56.23
N$712: IC53.24 IC54.24 IC55.24 IC56.24
N$713: IC53.25 IC54.25 IC55.25 IC56.25
N$714: IC53.26 IC54.26 IC55.26 IC56.26
N$715: IC53.27 IC54.27 IC55.27 IC56.27
N$716: IC53.28 IC54.28 IC55.28 IC56.28
N$717: IC53.29 IC54.29 IC55.29 IC56.29
N$718: IC53.30 IC54.30 IC55.30 IC56.30
N$719: IC53.31 IC54.31 IC55.31 IC56.31
N$720: IC53.32 IC54.32 IC55.32 IC56.32
N$721: IC53.33 IC54.33 IC55.33 IC56.33
N$722: IC53.34 IC54.34 IC55.34 IC56.34
N$723: IC53.35 IC54.35 IC55.35 IC56.35
N$724: IC53.36 IC54.36 IC55.36 IC56.36
N$725: IC53.37 IC54.37 IC55.37 IC56.37
N$726: IC53.38 IC54.38 IC55.38 IC56.38
N$727: IC53.39 IC54.39 IC55.39 IC56.39
N$728: IC53.40 IC54.40 IC55.40 IC56.40
N$729: IC53.41 IC54.41 IC55.41 IC56.41
N$730: IC53.42 IC54.42 IC55.42 IC56.42
N$731: IC57.1 IC58.1 IC59.1 IC60.1
N$732: IC57.2 IC58.2 IC59.2 IC60.2
N$733: IC57.3 IC58.3 IC59.3 IC60.3
N$734: IC57.4 IC58.4 IC59.4 IC60.4
N$735: IC57.5 IC58.5 IC59.5 IC60.5
N$736: IC57.6 IC58.6 IC59.6 IC60.6
N$737: IC57.7 IC58.7 IC59.7 IC60.7
N$738: IC57.8 IC58.8 IC59.8 IC60.8
N$739: IC57.9 IC58.9 IC59.9 IC60.9
N$740: IC57.10 IC58.10 IC59.10 IC60.10
N$741: IC57.11 IC58.11 IC59.11 IC60.11
N$742: IC57.12 IC58.12 IC59.12 IC60.12
N$743: IC57.13 IC58.13 IC59.13 IC60.13
N$744: IC57.14 IC58.14 IC59.14 IC60.14
N$745: IC57.15 IC58.15 IC59.15 IC60.15
N$746: IC57.16 IC58.16 IC59.16 IC60.16
N$747: IC57.17 IC58.17 IC59.17 IC60.17
N$748: IC57.18 IC58.18 IC59.18 IC60.18
N$749: IC57.19 IC58.19 IC59.19 IC60.19
N$750: IC57.20 IC58.20 IC59.20 IC60.20
N$751: IC57.21 IC58.21 IC59.21 IC60.21
N$752: IC57.22 IC58.22 IC59.22 IC60.22
N$753: IC57.23 IC58.23 IC59.23 IC60.23
N$754: IC57.24 IC58.24 IC59.24 IC60.24
N$755: IC57.25 IC58.25 IC59.25 IC60.25
N$756: IC57.26 IC58.26 IC59.26 IC60.26
N$757: IC57.27 IC58.27 IC59.27 IC60.27
N$758: IC57.28 IC58.28 IC59.28 IC60.28
N$759: IC57.29 IC58.29 IC59.29 IC60.29
N$760: IC57.30 IC58.30 IC59.30 IC60.30
N$761: IC57.31 IC58.31 IC59.31 IC60.31
N$762: IC57.32 IC58.32 IC59.32 IC60.32
N$763: IC57.33 IC58.33 IC59.33 IC60.33
N$764: IC57.34 IC58.34 IC59.34 IC60.34
N$765: IC57.35 IC58.35 IC59.35 IC60.35
N$766: IC57.36 IC58.36 IC59.36 IC60.36
N$767: IC57.37 IC58.37 IC59.37 IC60.37
N$768: IC57.38 IC58.38 IC59.38 IC60.38
N$769: IC57.39 IC58.39 IC59.39 IC60.39
N$770: IC57.40 IC58.40 IC59.40 IC60.40
N$771: IC57.41 IC58.41 IC59.41 IC60.41
N$772: IC57.42 IC58.42 IC59.42 IC60.42
N$773: IC61.1 IC62.1 IC63.1 IC64.1
N$774: IC61.2 IC62.2 IC63.2 IC64.2
N$775: IC61.3 IC62.3 IC63.3 IC64.3
N$776: IC61.4 IC62.4 IC63.4 IC64.4
N$777: IC61.5 IC62.5 IC63.5 IC64.5
N$778: IC61.6 IC62.6 IC63.6 IC64.6
N$779: IC61.7 IC62.7 IC63.7 IC64.7
N$780: IC61.8 IC62.8 IC63.8 IC64.8
N$781: IC61.9 IC62.9 IC63.9 IC64.9
N$782: IC61.10 IC62.10 IC63.10 IC64.10
N$783: IC61.11 IC62.11 IC63.11 IC64.11
N$784: IC61.12 IC62.12 IC63.12 IC64.12
N$785: IC61.13 IC62.13 IC63.13 IC64.13
N$786: IC61.14 IC62.14 IC63.14 IC64.14
N$787: IC61.15 IC62.15 IC63.15 IC64.15
N$788: IC61.16 IC62.16 IC63.16 IC64.16
N$789: IC61.17 IC62.17 IC63.17 IC64.17
N$790: IC61.18 IC62.18 IC63.18 IC64.18
N$791: IC61.19 IC62.19 IC63.19 IC64.19
N$792: IC61.20 IC62.20 IC63.20 IC64.20
N$793: IC61.21 IC62.21 IC63.21 IC64.21
N$794: IC61.22 IC62.22 IC63.22 IC64.22
N$795: IC61.23 IC62.23 IC63.23 IC64.23
N$796: IC61.24 IC62.24 IC63.24 IC64.24
N$797: IC61.25 IC62.25 IC63.25 IC64.25
N$798: IC61.26 IC62.26 IC63.26 IC64.26
N$799: IC61.27 IC62.27 IC63.27 IC64.27
N$800: IC61.28 IC62.28 IC63.28 IC64.28
N$801: IC61.29 IC62.29 IC63.29 IC64.29
N$802: IC61.30 IC62.30 IC63.30 IC64.30
N$803: IC61.31 IC62.31 IC63.31 IC64.31
N$804: IC61.32 IC62.32 IC63.32 IC64.32
N$805: IC61.33 IC62.33 IC63.33 IC64.33
N$806: IC61.34 IC62.34 IC63.34 IC64.34
N$807: IC61.35 IC62.35 IC63.35 IC64.35
N$808: IC61.36 IC62.36 IC63.36 IC64.36
N$809: IC61.37 IC62.37 IC63.37 IC64.37
N$810: IC61.38 IC62.38 IC63.38 IC64.38
N$811: IC61.39 IC62.39 IC63.39 IC64.39
N$812: IC61.40 IC62.40 IC63.40 IC64.40
N$813: IC61.41 IC62.41 IC63.41 IC64.41
N$814: IC61.42 IC62.42 IC63.42 IC64.42
N$815: IC65.1 IC66.1 IC67.1 IC68.1
N$816: IC65.2 IC66.2 IC67.2 IC68.2
N$817: IC65.3 IC66.3 IC67.3 IC68.3
N$818: IC65.4 IC66.4 IC67.4 IC68.4
N$819: IC65.5 IC66.5 IC67.5 IC68.5
N$820: IC65.6 IC66.6 IC67.6 IC68.6
N$821: IC65.7 IC66.7 IC67.7 IC68.7
N$822: IC65.8 IC66.8 IC67.8 IC68.8
N$823: IC65.9 IC66.9 IC67.9 IC68.9
N$824: IC65.10 IC66.10 IC67.10 IC68.10
N$825: IC65.11 IC66.11 IC67.11 IC68.11
N$826: IC65.12 IC66.12 IC67.12 IC68.12
N$827: IC65.13 IC66.13 IC67.13 IC68.13
N$828: IC65.14 IC66.14 IC67.14 IC68.14
N$829: IC65.15 IC66.15 IC67.15 IC68.15
N$830: IC65.16 IC66.16 IC67.16 IC68.16
N$831: IC65.17 IC66.17 IC67.17 IC68.17
N$832: IC65.18 IC66.18 IC67.18 IC68.18
N$833: IC65.19 IC66.19 IC67.19 IC68.19
N$834: IC65.20 IC66.20 IC67.20 IC68.20
N$835: IC65.21 IC66.21 IC67.21 IC68.21
N$836: IC65.22 IC66.22 IC67.22 IC68.22
N$837: IC65.23 IC66.23 IC67.23 IC68.23
N$838: IC65.24 IC66.24 IC67.24 IC68.24
N$839: IC65.25 IC66.25 IC67.25 IC68.25
N$840: IC65.26 IC66.26 IC67.26 IC68.26
N$841: IC65.27 IC66.27 IC67.27 IC68.27
N$842: IC65.28 IC66.28 IC67.28 IC68.28
N$843: IC65.29 IC66.29 IC67.29 IC68.29
N$844: IC65.30 IC66.30 IC67.30 IC68.30
N$845: IC65.31 IC66.31 IC67.31 IC68.31
N$846: IC65.32 IC66.32 IC67.32 IC68.32
N$847: IC65.33 IC66.33 IC67.33 IC68.33
N$848: IC65.34 IC66.34 IC67.34 IC68.34
N$849: IC65.35 IC66.35 IC67.35 IC68.35
N$850: IC65.36 IC66.36 IC67.36 IC68.36
N$851: IC65.37 IC66.37 IC67.37 IC68.37
N$852: IC65.38 IC66.38 IC67.38 IC68.38
N$853: IC65.39 IC66.39 IC67.39 IC68.39
N$854: IC65.40 IC66.40 IC67.40 IC68.40
N$855: IC65.41 IC66.41 IC67.41 IC68.41
N$856: IC65.42 IC66.42 IC67.42 IC68.42
N$857: IC69.1 IC70.1 IC71.1 IC72.1
N$858: IC69.2 IC70.2 IC71.2 IC72.2
N$859: IC69.3 IC70.3 IC71.3 IC72.3
N$860: IC69.4 IC70.4 IC71.4 IC72.4
N$861: IC69.5 IC70.5 IC71.5 IC72.5
N$862: IC69.6 IC70.6 IC71.6 IC72.6
N$863: IC69.7 IC70.7 IC71.7 IC72.7
N$864: IC69.8 IC70.8 IC71.8 IC72.8
N$865: IC69.9 IC70.9 IC71.9 IC72.9
N$866: IC69.10 IC70.10 IC71.10 IC72.10
N$867: IC69.11 IC70.11 IC71.11 IC72.11
N$868: IC69.12 IC70.12 IC71.12 IC72.12
N$869: IC69.13 IC70.13 IC71.13 IC72.13
N$870: IC69.14 IC70.14 IC71.14 IC72.14
N$871: IC69.15 IC70.15 IC71.15 IC72.15
N$872: IC69.16 IC70.16 IC71.16 IC72.16
N$873: IC69.17 IC70.17 IC71.17 IC72.17
N$874: IC69.18 IC70.18 IC71.18 IC72.18
N$875: IC69.19 IC70.19 IC71.19 IC72.19
N$876: IC69.20 IC70.20 IC71.20 IC72.20
N$877: IC69.21 IC70.21 IC71.21 IC72.21
N$878: IC69.22 IC70.22 IC71.22 IC72.22
N$879: IC69.23 IC70.23 IC71.23 IC72.23
N$880: IC69.24 IC70.24 IC71.24 IC72.24
N$881: IC69.25 IC70.25 IC71.25 IC72.25
N$882: IC69.26 IC70.26 IC71.26 IC72.26
N$883: IC69.27 IC70.27 IC71.27 IC72.27
N$884: IC69.28 IC70.28 IC71.28 IC72.28
N$885: IC69.29 IC70.29 IC71.29 IC72.29
N$886: IC69.30 IC70.30 IC71.30 IC72.30
N$887: IC69.31 IC70.31 IC71.31 IC72.31
N$888: IC69.32 IC70.32 IC71.32 IC72.32
N$889: IC69.33 IC70.33 IC71.33 IC72.33
N$890: IC69.34 IC70.34 IC71.34 IC72.34
N$891: IC69.35 IC70.35 IC71.35 IC72.35
N$892: IC69.36 IC70.36 IC71.36 IC72.36
N$893: IC69.37 IC70.37 IC71.37 IC72.37
N$894: IC69.38 IC70.38 IC71.38 IC72.38
N$895: IC69.39 IC70.39 IC71.39 IC72.39
N$896: IC69.40 IC70.40 IC71.40 IC72.40
N$897: IC69.41 IC70.41 IC71.41 IC72.41
N$898: IC69.42 IC70.42 IC71.42 IC72.42
N$899: IC73.1 IC74.1 IC75.1 IC76.1
N$900: IC73.2 IC74.2 IC75.2 IC76.2
N$901: IC73.3 IC74.3 IC75.3 IC76.3
N$902: IC73.4 IC74.4 IC75.4 IC76.4
N$903: IC73.5 IC74.5 IC75.5 IC76.5
N$904: IC73.6 IC74.6 IC75.6 IC76.6
N$905: IC73.7 IC74.7 IC75.7 IC76.7
N$906: IC73.8 IC74.8 IC75.8 IC76.8
N$907: IC73.9 IC74.9 IC75.9 IC76.9
N$908: IC73.10 IC74.10 IC75.10 IC76.10
N$909: IC73.11 IC74.11 IC75.11 IC76.11
N$910: IC73.12 IC74.12 IC75.12 IC76.12
N$911: IC73.13 IC74.13 IC75.13 IC76.13
N$912: IC73.14 IC74.14 IC75.14 IC76.14
N$913: IC73.15 IC74.15 IC75.15 IC76.15
N$914: IC73.16 IC74.16 IC75.16 IC76.16
N$915: IC73.17 IC74.17 IC75.17 IC76.17
N$916: IC73.18 IC74.18 IC75.18 IC76.18
N$917: IC73.19 IC74.19 IC75.19 IC76.19
N$918: IC73.20 IC74.20 IC75.20 IC76.20
N$919: IC73.21 IC74.21 IC75.21 IC76.21
N$920: IC73.22 IC74.22 IC75.22 IC76.22
N$921: IC73.23 IC74.23 IC75.23 IC76.23
N$922: IC73.24 IC74.24 IC75.24 IC76.24
N$923: IC73.25 IC74.25 IC75.25 IC76.25
N$924: IC73.26 IC74.26 IC75.26 IC76.26
N$925: IC73.27 IC74.27 IC75.27 IC76.27
N$926: IC73.28 IC74.28 IC75.28 IC76.28
N$927: IC73.29 IC74.29 IC75.29 IC76.29
N$928: IC73.30 IC74.30 IC75.30 IC76.30
N$929: IC73.31 IC74.31 IC75.31 IC76.31
N$930: IC73.32 IC74.32 IC75.32 IC76.32
N$931: IC73.33 IC74.33 IC75.33 IC76.33
N$932: IC73.34 IC74.34 IC75.34 IC76.34
N$933: IC73.35 IC74.35 IC75.35 IC76.35
N$934: IC73.36 IC74.36 IC75.36 IC76.36
N$935: IC73.37 IC74.37 IC75.37 IC76.37
N$936: IC73.38 IC74.38 IC75.38 IC76.38
N$937: IC73.39 IC74.39 IC75.39 IC76.39
N$938: IC73.40 IC74.40 IC75.40 IC76.40
N$939: IC73.41 IC74.41 IC75.41 IC76.41
N$940: IC73.42 IC74.42 IC75.42 IC76.42
N$941: IC77.1 IC78.1 IC79.1 IC80.1
N$942: IC77.2 IC78.2 IC79.2 IC80.2
N$943: IC77.3 IC78.3 IC79.3 IC80.3
N$944: IC77.4 IC78.4 IC79.4 IC80.4
N$945: IC77.5 IC78.5 IC79.5 IC80.5
N$946: IC77.6 IC78.6 IC79.6 IC80.6
N$947: IC77.7 IC78.7 IC79.7 IC80.7
N$948: IC77.8 IC78.8 IC79.8 IC80.8
N$949: IC77.9 IC78.9 IC79.9 IC80.9
N$950: IC77.10 IC78.10 IC79.10 IC80.10
N$951: IC77.11 IC78.11 IC79.11 IC80.11
N$952: IC77.12 IC78.12 IC79.12 IC80.12
N$953: IC77.13 IC78.13 IC79.13 IC80.13
N$954: IC77.14 IC78.14 IC79.14 IC80.14
N$955: IC77.15 IC78.15 IC79.15 IC80.15
N$956: IC77.16 IC78.16 IC79.16 IC80.16
N$957: IC77.17 IC78.17 IC79.17 IC80.17
N$958: IC77.18 IC78.18 IC79.18 IC80.18
N$959: IC77.19 IC78.19 IC79.19 IC80.19
N$960: IC77.20 IC78.20 IC79.20 IC80.20
N$961: IC77.21 IC78.21 IC79.21 IC80.21
N$962: IC77.22 IC78.22 IC79.22 IC80.22
N$963: IC77.23 IC78.23 IC79.23 IC80.23
N$964: IC77.24 IC78.24 IC79.24 IC80.24
N$965: IC77.25 IC78.25 IC79.25 IC80.25
N$966: IC77.26 IC78.26 IC79.26 IC80.26
N$967: IC77.27 IC78.27 IC79.27 IC80.27
N$968: IC77.28 IC78.28 IC79.28 IC80.28
N$969: IC77.29 IC78.29 IC79.29 IC80.29
N$970: IC77.30 IC78.30 IC79.30 IC80.30
N$971: IC77.31 IC78.31 IC79.31 IC80.31
N$972: IC77.32 IC78.32 IC79.32 IC80.32
N$973: IC77.33 IC78.33 IC79.33 IC80.33
N$974: IC77.34 IC78.34 IC79.34 IC80.34
N$975: IC77.35 IC78.35 IC79.35 IC80.35
N$976: IC77.36 IC78.36 IC79.36 IC80.36
N$977: IC77.37 IC78.37 IC79.37 IC80.37
N$978: IC77.38 IC78.38 IC79.38 IC80.38
N$979: IC77.39 IC78.39 IC79.39 IC80.39
N$980: IC77.40 IC78.40 IC79.40 IC80.40
N$981: IC77.41 IC78.41 IC79.41 IC80.41
N$982: IC77.42 IC78.42 IC79.42 IC80.42
N$983: IC81.1 IC82.1 IC83.1 IC84.1
N$984: IC81.2 IC82.2 IC83.2 IC84.2
N$985: IC81.3 IC82.3 IC83.3 IC84.3
N$986: IC81.4 IC82.4 IC83.4 IC84.4
N$987: IC81.5 IC82.5 IC83.5 IC84.5
N$988: IC81.6 IC82.6 IC83.6 IC84.6
N$989: IC81.7 IC82.7 IC83.7 IC84.7
N$990: IC81.8 IC82.8 IC83.8 IC84.8
N$991: IC81.9 IC82.9 IC83.9 IC84.9
N$992: IC81.10 IC82.10 IC83.10 IC84.10
N$993: IC81.11 IC82.11 IC83.11 IC84.11
N$994: IC81.12 IC82.12 IC83.12 IC84.12
N$995: IC81.13 IC82.13 IC83.13 IC84.13
N$996: IC81.14 IC82.14 IC83.14 IC84.14
N$997: IC81.15 IC82.15 IC83.15 IC84.15
N$998: IC81.16 IC82.16 IC83.16 IC84.16
N$999: IC81.17 IC82.17 IC83.17 IC84.17
N$1000: IC81.18 IC82.18 IC83.18 IC84.18
N$1001: IC81.19 IC82.19 IC83.19 IC84.19
N$1002: IC81.20 IC82.20 IC83.20 IC84.20
N$1003: IC81.21 IC82.21 IC83.21 IC84.21
N$1004: IC81.22 IC82.22 IC83.22 IC84.22
N$1005: IC81.23 IC82.23 IC83.23 IC84.23
N$1006: IC81.24 IC82.24 IC83.24 IC84.24
N$1007: IC81.25 IC82.25 IC83.25 IC84.25
N$1008: IC81.26 IC82.26 IC83.26 IC84.26
N$1009: IC81.27 IC82.27 IC83.27 IC84.27
N$1010: IC81.28 IC82.28 IC83.28 IC84.28
N$1011: IC81.29 IC82.29 IC83.29 IC84.29
N$1012: IC81.30 IC82.30 IC83.30 IC84.30
N$1013: IC81.31 IC82.31 IC83.31 IC84.31
N$1014: IC81.32 IC82.32 IC83.32 IC84.32
N$1015: IC81.33 IC82.33 IC83.33 IC84.33
N$1016: IC81.34 IC82.34 IC83.34 IC84.34
N$1017: IC81.35 IC82.35 IC83.35 IC84.35
N$1018: IC81.36 IC82.36 IC83.36 IC84.36
N$1019: IC81.37 IC82.37 IC83.37 IC84.37
N$1020: IC81.38 IC82.38 IC83.38 IC84.38
N$1021: IC81.39 IC82.39 IC83.39 IC84.39
N$1022: IC81.40 IC82.40 IC83.40 IC84.40
N$1023: IC81.41 IC82.41 IC83.41 IC84.41
N$1024: IC81.42 IC82.42 IC83.42 IC84.42
N$1025: IC85.1 IC86.1 IC87.1 IC88.1
N$1026: IC85.2 IC86.2 IC87.2 IC88.2
N$1027: IC85.3 IC86.3 IC87.3 IC88.3
N$1028: IC85.4 IC86.4 IC87.4 IC88.4
N$1029: IC85.5 IC86.5 IC87.5 IC88.5
N$1030: IC85.6 IC86.6 IC87.6 IC88.6
N$1031: IC85.7 IC86.7 IC87.7 IC88.7
N$1032: IC85.8 IC86.8 IC87.8 IC88.8
N$1033: IC85.9 IC86.9 IC87.9 IC88.9
N$1034: IC85.10 IC86.10 IC87.10 IC88.10
N$1035: IC85.11 IC86.11 IC87.11 IC88.11
N$1036: IC85.12 IC86.12 IC87.12 IC88.12
N$1037: IC85.13 IC86.13 IC87.13 IC88.13
N$1038: IC85.14 IC86.14 IC87.14 IC88.14
N$1039: IC85.15 IC86.15 IC87.15 IC88.15
N$1040: IC85.16 IC86.16 IC87.16 IC88.16
N$1041: IC85.17 IC86.17 IC87.17 IC88.17
N$1042: IC85.18 IC86.18 IC87.18 IC88.18
N$1043: IC85.19 IC86.19 IC87.19 IC88.19
N$1044: IC85.20 IC86.20 IC87.20 IC88.20
N$1045: IC85.21 IC86.21 IC87.21 IC88.21
N$1046: IC85.22 IC86.22 IC87.22 IC88.22
N$1047: IC85.23 IC86.23 IC87.23 IC88.23
N$1048: IC85.24 IC86.24 IC87.24 IC88.24
N$1049: IC85.25 IC86.25 IC87.25 IC88.25
N$1050: IC85.26 IC86.26 IC87.26 IC88.26
N$1051: IC85.27 IC86.27 IC87.27 IC88.27
N$1052: IC85.28 IC86.28 IC87.28 IC88.28
N$1053: IC85.29 IC86.29 IC87.29 IC88.29
N$1054: IC85.30 IC86.30 IC87.30 IC88.30
N$1055: IC85.31 IC86.31 IC87.31 IC88.31
N$1056: IC85.32 IC86.32 IC87.32 IC88.32
N$1057: IC85.33 IC86.33 IC87.33 IC88.33
N$1058: IC85.34 IC86.34 IC87.34 IC88.34
N$1059: IC85.35 IC86.35 IC87.35 IC88.35
N$1060: IC85.36 IC86.36 IC87.36 IC88.36
N$1061: IC85.37 IC86.37 IC87.37 IC88.37
N$1062: IC85.38 IC86.38 IC87.38 IC88.38
N$1063: IC85.39 IC86.39 IC87.39 IC88.39
N$1064: IC85.40 IC86.40 IC87.40 IC88.40
N$1065: IC85.41 IC86.41 IC87.41 IC88.41
N$1066: IC85.42 IC86.42 IC87.42 IC88.42
N$1067: IC89.1 IC90.1 IC91.1 IC92.1
N$1068: IC89.2 IC90.2 IC91.2 IC92.2
N$1069: IC89.3 IC90.3 IC91.3 IC92.3
N$1070: IC89.4 IC90.4 IC91.4 IC92.4
N$1071: IC89.5 IC90.5 IC91.5 IC92.5
N$1072: IC89.6 IC90.6 IC91.6 IC92.6
N$1073: IC89.7 IC90.7 IC91.7 IC92.7
N$1074: IC89.8 IC90.8 IC91.8 IC92.8
N$1075: IC89.9 IC90.9 IC91.9 IC92.9
N$1076: IC89.10 IC90.10 IC91.10 IC92.10
N$1077: IC89.11 IC90.11 IC91.11 IC92.11
N$1078: IC89.12 IC90.12 IC91.12 IC92.12
N$1079: IC89.13 IC90.13 IC91.13 IC92.13
N$1080: IC89.14 IC90.14 IC91.14 IC92.14
N$1081: IC89.15 IC90.15 IC91.15 IC92.15
N$1082: IC89.16 IC90.16 IC91.16 IC92.16
N$1083: IC89.17 IC90.17 IC91.17 IC92.17
N$1084: IC89.18 IC90.18 IC91.18 IC92.18
N$1085: IC89.19 IC90.19 IC91.19 IC92.19
N$1086: IC89.20 IC90.20 IC91.20 IC92.20
N$1087: IC89.21 IC90.21 IC91.21 IC92.21
N$1088: IC89.22 IC90.22 IC91.22 IC92.22
N$1089: IC89.23 IC90.23 IC91.23 IC92.23
N$1090: IC89.24 IC90.24 IC91.24 IC92.24
N$1091: IC89.25 IC90.25 IC91.25 IC92.25
N$1092: IC89.26 IC90.26 IC91.26 IC92.26
N$1093: IC89.27 IC90.27 IC91.27 IC92.27
N$1094: IC89.28 IC90.28 IC91.28 IC92.28
N$1095: IC89.29 IC90.29 IC91.29 IC92.29
N$1096: IC89.30 IC90.30 IC91.30 IC92.30
N$1097: IC89.31 IC90.31 IC91.31 IC92.31
N$1098: IC89.32 IC90.32 IC91.32 IC92.32
N$1151: SV1.A U$2.1
N$1152: SV1.C U$2.2
N$1153: SV1.E U$2.3
N$1154: SV1.H U$2.4
N$1155: SV1.K U$2.5
N$1156: SV1.M U$2.6
N$1157: SV1.P U$2.7
N$1158: SV1.S U$2.8
N$1159: SV1.U U$2.9
N$1160: SV1.W U$2.10
N$1161: SV1.Y U$2.11
N$1162: SV1.AA U$2.12
N$1163: SV1.CC U$2.13
N$1164: SV1.EE U$2.14
N$1165: SV1.HH U$2.15
N$1166: SV1.KK U$2.16
N$1167: SV1.MM U$2.17
N$1168: SV1.PP U$2.18
N$1169: SV1.SS U$2.19
N$1170: SV1.UU U$2.20
N$1171: SV1.B U$4.1
N$1172: SV1.D U$4.2
N$1173: SV1.F U$4.3
N$1174: SV1.J U$4.4
N$1175: SV1.L U$4.5
N$1176: SV1.N U$4.6
N$1177: SV1.R U$4.7
N$1178: SV1.T U$4.8
N$1179: SV1.V U$4.9
N$1180: SV1.X U$4.10
N$1181: SV1.Z U$4.11
N$1182: SV1.BB U$4.12
N$1183: SV1.DD U$4.13
N$1184: SV1.FF U$4.14
N$1185: SV1.JJ U$4.15
N$1186: SV1.LL U$4.16
N$1187: SV1.NN U$4.17
N$1188: SV1.RR U$4.18
N$1189: SV1.TT U$4.19
N$1190: SV1.VV U$4.20
VCC [supply]: U$1.AA2 U$5.1

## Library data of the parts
IC1-IC88 = ic-package:DIL42: Dual In Line
IC89-IC92 = ic-package:DIL32: Dual In Line
SV1 = dec-con:DEC40PIN: PIN HEADER
U$1 = dec-con:QUAD: Quad-Height DEC board
U$2 U$4 = dec-con:MA20-1
U$3 U$5-U$7 U$9-U$12 = dec-con:MA18-1
U$8 = dec-con:OUTLINE-*: Board outlines for DEC boards.

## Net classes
1 supply: width 0.508 mm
